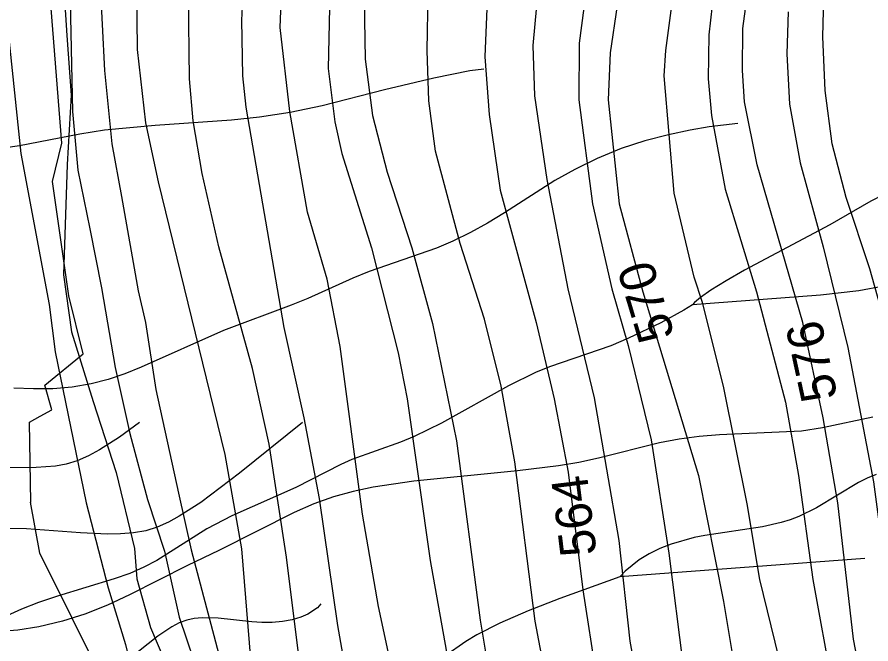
# Model space of a CAD drawing. Extents: x -709584 to -702006, y -1161789 to -1157496.
# Drawn here: x -709283.2 to -709047.8, y -1161005.5 to -1160832.7 of the extents above; entities that cross this region are included whole.
import ezdxf

# ---------------------------------------------------------------- set-up
doc = ezdxf.new("R2010")
doc.units = 0
for name, color, linetype in [('103_hranice KÚ', 7, 'Continuous'), ('120_vrstevnice hlavní', 7, 'Continuous'), ('121_vrstevnice hlavní_popis', 7, 'Continuous'), ('122_vrstevnice základní', 7, 'Continuous'), ('408_BPEJ_linie', 7, 'Continuous'), ('411_akumulovaný odtok', 7, 'Continuous')]:
    doc.layers.add(name, color=color, linetype=linetype)

msp = doc.modelspace()

# ---------------------------------------------------------------- linework, layer by layer
at = {"layer": '103_hranice KÚ'}
msp.add_lwpolyline([(-709272.02, -1160799.36), (-709269.54, -1160837.72), (-709268.34, -1160854.2), (-709269.41, -1160873.36), (-709270.41, -1160903.76), (-709268.23, -1160919.43), (-709262.21, -1160938.65), (-709255.95, -1160958.22), (-709250.87, -1160979.18), (-709250.21, -1160987.55), (-709246.42, -1161000.99), (-709242.46, -1161010.31), (-709232.98, -1161027.29), (-709222.38, -1161046.02), (-709218.04, -1161058.04), (-709217.06, -1161067.22), (-709216.15, -1161082.04), (-709217.68, -1161092.12), (-709215.78, -1161106.54), (-709203.57, -1161124.53), (-709202.27, -1161126.44), (-709193.49, -1161139.37), (-709234.65, -1161164.22), (-709251.02, -1161179.72)], dxfattribs=at)
at = {"layer": '120_vrstevnice hlavní'}
for points in [[(-709250.42, -1160816.46), (-709250.13, -1160841.63), (-709247.82, -1160861.88), (-709244.35, -1160878.08), (-709225.98, -1160953.3), (-709221.35, -1160979.33), (-709218.89, -1161009.71), (-709211.8, -1161040.08), (-709208.62, -1161048.76), (-709200.81, -1161066.12), (-709185.48, -1161096.49), (-709177.23, -1161108.79), (-709155.25, -1161134.97), (-709151.92, -1161140.18), (-709150.18, -1161145.96), (-709151.05, -1161152.62), (-709152.35, -1161156.96), (-709157.13, -1161165.64), (-709167.98, -1161177.06)], [(-708894.31, -1161154.64), (-708908.19, -1161150.59), (-708929.31, -1161139.45), (-708935.1, -1161135.84), (-708945.08, -1161127.59), (-708978.06, -1161094.9), (-708986.59, -1161084.92), (-709008.87, -1161053.97), (-709019.43, -1161034.3), (-709023.62, -1161024.46), (-709030.71, -1160999.87), (-709032.59, -1160990.04), (-709042.57, -1160921.76), (-709048.07, -1160902.09), (-709054.57, -1160882.42), (-709058.48, -1160867.67), (-709060.36, -1160852.91), (-709061.08, -1160838.16), (-709060.65, -1160823.7)], [(-709187.5, -1160828.03), (-709187.21, -1160844.24), (-709185.19, -1160859.86), (-709181.14, -1160875.48), (-709174.34, -1160896.31), (-709168.7, -1160917.14), (-709162.05, -1160949.54), (-709155.54, -1160999), (-709153.66, -1161010), (-709148.45, -1161031.98), (-709141.51, -1161053.97), (-709135.14, -1161070.46), (-709116.19, -1161114.43), (-709104.33, -1161135.84), (-709079.02, -1161168.53), (-709074.53, -1161173.16)], [(-709117.78, -1160829.48), (-709119.66, -1160842.5), (-709120.24, -1160855.52), (-709117.21, -1160884.16), (-709110.7, -1160908.46), (-709095.36, -1160959.08), (-709088.42, -1160993.8), (-709083.36, -1161024.17), (-709074.34, -1161055.36), (-709062.5, -1161079.58), (-709039.24, -1161114.57), (-709034.76, -1161120.51), (-708995.85, -1161166.21), (-708983.41, -1161178.65)]]:
    msp.add_lwpolyline(points, dxfattribs=at)
at = {"layer": '122_vrstevnice základní'}
for points in [[(-709288.17, -1160813.86), (-709282.24, -1160870.27), (-709274.43, -1160911.93), (-709272.7, -1160924.95), (-709264.16, -1160966.6), (-709258.09, -1160990.04), (-709253.32, -1161005.66), (-709243.77, -1161044.42), (-709240.59, -1161061.78), (-709239.86, -1161073.35), (-709241.89, -1161086.66), (-709245.07, -1161094.47), (-709251.72, -1161105.17), (-709257.08, -1161110.67), (-709269.81, -1161117.9), (-709290.63, -1161126.29), (-709303.65, -1161133.96), (-709321.88, -1161148.13), (-709347.33, -1161172.87)], [(-709099.56, -1161178.36), (-709099.99, -1161172), (-709102.16, -1161167.37), (-709120.96, -1161143.07), (-709137.17, -1161115.3), (-709163.35, -1161060.04), (-709168.99, -1161046.16), (-709175.5, -1161027.64), (-709180.12, -1161011.44), (-709183.6, -1160995.24), (-709187.94, -1160969.79), (-709194.16, -1160923.5), (-709197.77, -1160904.99), (-709203.12, -1160886.47), (-709208.04, -1160858.7), (-709210.65, -1160835.56), (-709209.92, -1160817.04)], [(-708958.82, -1161176.92), (-708979.36, -1161163.9), (-708987.17, -1161158.26), (-708993.39, -1161152.76), (-709001.06, -1161144.8), (-709013.21, -1161130.2), (-709033.6, -1161102.14), (-709041.56, -1161089.55), (-709046.62, -1161079.72), (-709056.74, -1161063.52), (-709062.29, -1161052.26), (-709067.83, -1161036.6), (-709071.06, -1161017.81), (-709078.44, -1160987.72), (-709081.91, -1160966.89), (-709088.42, -1160934.49), (-709094.21, -1160911.35), (-709096.52, -1160904.41), (-709102.02, -1160881.26), (-709104.77, -1160848.86), (-709104.33, -1160841.92), (-709101.29, -1160819.07)], [(-709260.4, -1160821.96), (-709259.1, -1160847.42), (-709257.08, -1160867.67), (-709254.47, -1160882.13), (-709249.84, -1160908.17), (-709247.82, -1160916.85), (-709244.93, -1160935.36), (-709238.71, -1160964), (-709235.23, -1160979.62), (-709225.54, -1161016.07)], [(-709196.9, -1160821.67), (-709197.48, -1160846.84), (-709195.6, -1160861.59), (-709193.72, -1160870.27), (-709185.48, -1160896.31), (-709178.1, -1160925.24), (-709175.64, -1160937.96), (-709169.28, -1160982.52), (-709163.06, -1161017.52), (-709160.31, -1161030.25), (-709155.97, -1161046.16), (-709151.2, -1161058.89)], [(-709125.88, -1160821.67), (-709128.2, -1160839.9), (-709128.34, -1160855.52), (-709124.58, -1160884.16), (-709119.23, -1160907.59), (-709114.75, -1160923.21), (-709108.38, -1160949.25), (-709103.46, -1160980.49), (-709099.56, -1161011.73), (-709096.38, -1161027.93), (-709091.89, -1161045.29), (-709083.5, -1161071.33), (-709080.9, -1161077.11), (-709071.5, -1161094.47), (-709051.83, -1161126.29), (-709036.06, -1161147.12), (-709006.26, -1161180.97)], [(-709268.65, -1160823.98), (-709267.92, -1160858.7), (-709266.48, -1160874.9), (-709263.15, -1160891.1), (-709259.97, -1160907.3), (-709256.21, -1160929.29), (-709252.16, -1160947.51), (-709247.24, -1160965.74), (-709242.61, -1160979.91), (-709238.56, -1160998.14), (-709232.34, -1161016.36)], [(-709220.91, -1160824.27), (-709221.35, -1160833.53), (-709221.06, -1160848.86), (-709220.19, -1160857.54), (-709209.63, -1160918.29), (-709204.14, -1160943.17), (-709199.94, -1160965.45), (-709194.88, -1161000.45), (-709189.82, -1161029.09), (-709184.75, -1161048.18), (-709178.68, -1161064.09), (-709165.66, -1161089.55), (-709149.75, -1161111.83), (-709139.62, -1161127.16), (-709131.96, -1161136.42), (-709123.28, -1161151.75), (-709120.1, -1161160.43), (-709119.37, -1161166.21), (-709120.39, -1161172.29), (-709121.54, -1161175.47)], [(-709030.85, -1161175.04), (-709046.18, -1161156.96), (-709080.03, -1161108.93), (-709087.55, -1161095.05), (-709097.39, -1161071.91), (-709102.89, -1161055.71), (-709109.1, -1161032.56), (-709114.17, -1161004.79), (-709117.2, -1160977.02), (-709124, -1160937.68), (-709131.23, -1160907.59), (-709137.02, -1160877.5), (-709140.49, -1160854.36), (-709140.93, -1160840.47), (-709139.48, -1160824.56)], [(-709028.97, -1161066.7), (-709039.39, -1161048.47), (-709045.03, -1161035.46), (-709048.5, -1161025.04), (-709052.55, -1161004.21), (-709056.89, -1160966.6), (-709060.94, -1160943.17), (-709066.58, -1160916.85), (-709079.16, -1160873.45), (-709082.64, -1160856.09), (-709083.21, -1160847.42), (-709083.07, -1160835.84), (-709081.62, -1160824.85)], [(-709173.76, -1161204.69), (-709136.44, -1161161.58), (-709134.56, -1161158.11), (-709133.84, -1161151.46), (-709136.88, -1161144.23), (-709148.16, -1161129.33), (-709159.44, -1161111.83), (-709173.04, -1161093.6), (-709186.92, -1161072.77), (-709193.14, -1161059.76), (-709200.67, -1161036.32), (-709204.71, -1161015.49), (-709208.91, -1160981.65), (-709213.68, -1160950.4), (-709218.31, -1160929.57), (-709227.57, -1160896.02), (-709232.2, -1160875.77), (-709234.66, -1160861.3), (-709235.67, -1160849.73), (-709235.96, -1160826.59)], [(-709047.92, -1161186.75), (-709078.01, -1161154.64), (-709086.83, -1161142.49), (-709103.03, -1161117.03), (-709115.9, -1161091.87), (-709125.45, -1161066.41), (-709131.96, -1161043.27), (-709140.35, -1160999.29), (-709145.99, -1160955.32), (-709149.75, -1160934.49), (-709154.38, -1160915.98), (-709161.03, -1160895.15), (-709167.83, -1160869.69), (-709169.71, -1160855.81), (-709170.14, -1160841.92), (-709169.85, -1160826.01)], [(-709153.66, -1160830.35), (-709154.23, -1160843.66), (-709153.08, -1160859.57), (-709150.04, -1160880.4), (-709140.06, -1160916.85), (-709135.14, -1160937.96), (-709131.23, -1160958.21), (-709127.19, -1160990.61), (-709123.42, -1161014.92), (-709117.78, -1161045.29), (-709112.87, -1161065.54), (-709107.95, -1161081.74), (-709104.19, -1161091.87), (-709095.8, -1161110.09), (-709077.57, -1161141.33), (-709066.44, -1161156.96)], [(-709091.6, -1160829.48), (-709092.47, -1160837.58), (-709092.62, -1160849.73), (-709091.75, -1160859.86), (-709087.99, -1160880.11), (-709079.31, -1160908.46), (-709071.35, -1160938.83), (-709067.74, -1160959.08), (-709063.83, -1160987.72), (-709058.33, -1161017.52), (-709055.15, -1161029.67), (-709045.75, -1161053.97), (-709037.65, -1161069.3), (-709018.27, -1161100.26), (-709005.97, -1161118.19), (-708995.85, -1161131.5), (-708982.25, -1161146.69), (-708972.56, -1161155.65), (-708955.35, -1161167.8), (-708936.54, -1161178.65)], [(-709070.63, -1160831.22), (-709070.92, -1160842.79), (-709070.2, -1160856.67), (-709067.3, -1160872.87), (-709060.94, -1160896.02), (-709054.14, -1160923.79), (-709047.05, -1160960.82), (-709042.71, -1160993.22), (-709040.11, -1161007.1), (-709035.48, -1161025.62), (-709026.08, -1161048.76), (-709020.44, -1161058.45), (-708989.05, -1161101.99), (-708964.17, -1161129.76), (-708951.59, -1161141.77), (-708944.35, -1161147.7)]]:
    msp.add_lwpolyline(points, dxfattribs=at)
at = {"layer": '408_BPEJ_linie'}
msp.add_lwpolyline([(-709259, -1161016.5), (-709277, -1160980.5), (-709279.55, -1160966.46), (-709279.46, -1160966.54), (-709279.83, -1160944.38), (-709276.84, -1160942.75), (-709273.64, -1160941.01), (-709275.62, -1160934.19), (-709265, -1160925.5), (-709269, -1160909.5), (-709273.5, -1160878), (-709270.89, -1160867.4), (-709278.1, -1160776.85)], dxfattribs=at)
at = {"layer": '411_akumulovaný odtok'}
msp.add_line((-709049.49, -1160982), (-709116.99, -1160987), dxfattribs=at)
for points in [[(-709154.49, -1160847), (-709158.39, -1160847.52), (-709168.31, -1160849.49), (-709181.95, -1160852.72), (-709199.08, -1160857.18), (-709207.93, -1160858.97), (-709216.4, -1160860.25), (-709224.07, -1160861.06), (-709245.18, -1160862.54), (-709259.1, -1160863.9), (-709265.92, -1160864.92), (-709282.56, -1160868.17), (-709297.21, -1160870.26)], [(-709084.49, -1160862), (-709092.35, -1160862.96), (-709097.59, -1160863.87), (-709103.61, -1160865.15), (-709110.08, -1160866.83), (-709116.69, -1160868.96), (-709123.29, -1160871.65), (-709129.44, -1160874.66), (-709134.9, -1160877.75), (-709148.82, -1160886.65), (-709153.48, -1160889.47), (-709158.22, -1160892.11), (-709163.07, -1160894.48), (-709167.61, -1160896.36), (-709186.15, -1160902.87), (-709190.69, -1160904.66), (-709203.09, -1160910.24), (-709207.66, -1160912.11), (-709226.35, -1160919.12), (-709248.99, -1160929.18), (-709253.53, -1160931.01), (-709258.12, -1160932.6), (-709262.77, -1160933.85), (-709268.02, -1160934.73), (-709273.35, -1160935.15), (-709278.73, -1160935.22), (-709284.14, -1160935)], [(-709044.23, -1160881.62), (-709047.8, -1160883.46), (-709059.09, -1160889.98), (-709082.61, -1160902.48), (-709087.74, -1160905.38), (-709091.96, -1160908), (-709094.75, -1160909.98), (-709096.47, -1160911.38), (-709096.99, -1160912)], [(-708924.49, -1160897), (-708925.71, -1160896.82), (-708926.97, -1160896.39), (-708935.5, -1160893.01), (-708939.11, -1160892), (-708942.91, -1160891.41), (-708961.24, -1160890.31), (-708985.82, -1160888.48), (-708992.8, -1160888.22), (-708999.67, -1160888.41), (-709003.02, -1160888.8), (-709006.3, -1160889.48), (-709009.55, -1160890.53), (-709012.72, -1160891.88), (-709015.84, -1160893.43), (-709028.15, -1160900.42), (-709034.42, -1160903.65), (-709037.65, -1160904.99), (-709040.92, -1160906.05), (-709044.26, -1160906.89), (-709051.1, -1160908.12), (-709061.65, -1160909.34), (-709096.99, -1160912)], [(-709096.99, -1160912), (-709099.39, -1160913.52), (-709105.74, -1160916.99), (-709114.6, -1160921.25), (-709119.53, -1160923.31), (-709136.39, -1160929.11), (-709140.23, -1160930.69), (-709147.75, -1160934.4), (-709166.24, -1160944.61), (-709173.73, -1160948.3), (-709177.53, -1160949.89), (-709190.91, -1160954.69), (-709193.94, -1160956.08), (-709206.36, -1160962.4), (-709224.03, -1160970.25), (-709230.88, -1160973.76), (-709244.74, -1160982.48), (-709248.3, -1160984.4), (-709252.16, -1160986.07), (-709256.44, -1160987.57), (-709272.08, -1160992.36), (-709277.3, -1160994.1), (-709282.06, -1160995.92), (-709286.1, -1160997.77)], [(-709047.26, -1160943.04), (-709061.13, -1160945.97), (-709066.95, -1160946.83), (-709089.56, -1160947.87), (-709095.1, -1160948.37), (-709100.63, -1160949.07), (-709106.11, -1160950.07), (-709122.86, -1160954.35), (-709128.36, -1160955.48), (-709133.94, -1160956.4), (-709145.26, -1160957.81), (-709173.82, -1160960.66), (-709185.07, -1160962.31), (-709190.59, -1160963.46), (-709195.98, -1160964.95), (-709201.44, -1160966.93), (-709206.78, -1160969.25), (-709227.62, -1160979.75), (-709236.27, -1160983.9), (-709252.23, -1160992.03), (-709258.33, -1160994.81), (-709264.54, -1160997.28), (-709270.67, -1160999.27), (-709277.22, -1161000.81), (-709283.02, -1161001.72), (-709287.68, -1161002.13)], [(-709249.49, -1160944.5), (-709254.98, -1160948.56), (-709260.48, -1160952.05), (-709263.53, -1160953.66), (-709266.64, -1160955), (-709269.73, -1160955.95), (-709272.6, -1160956.48), (-709277.93, -1160956.88), (-709286.07, -1160957.01), (-709313.37, -1160956.91), (-709318.76, -1160957.15), (-709324.05, -1160957.77), (-709326.63, -1160958.33), (-709329.12, -1160959.09), (-709333.96, -1160961.11), (-709338.7, -1160963.51), (-709352.83, -1160971.35), (-709358.75, -1160973.95), (-709362.03, -1160975.06), (-709365.33, -1160975.94), (-709368.31, -1160976.5), (-709373.43, -1160977.02), (-709376.99, -1160977)], [(-709204.49, -1160944.5), (-709221.86, -1160958.44), (-709232.58, -1160966.54), (-709238.51, -1160970.34), (-709241.5, -1160971.94), (-709244.56, -1160973.29), (-709247.71, -1160974.3), (-709251.16, -1160974.93), (-709254.72, -1160975.21), (-709258.34, -1160975.25), (-709265.71, -1160974.89), (-709280.63, -1160973.79), (-709288.07, -1160973.7)], [(-709046.35, -1160958.83), (-709048.8, -1160959.81), (-709051.19, -1160961), (-709062.79, -1160968), (-709067.61, -1160970.42), (-709070.05, -1160971.32), (-709072.55, -1160972.05), (-709077.7, -1160973.2), (-709093.56, -1160975.6), (-709096.49, -1160976.17), (-709102.87, -1160978), (-709106.02, -1160979.24), (-709108.95, -1160980.69), (-709111.66, -1160982.38), (-709115.59, -1160985.5), (-709116.99, -1160987)], [(-709116.99, -1160987), (-709133.55, -1160993.04), (-709142.34, -1160996.44), (-709150.15, -1160999.78), (-709156.45, -1161003.05), (-709159.46, -1161004.89), (-709165.3, -1161008.91)], [(-709199.49, -1160994.5), (-709200.39, -1160995.55), (-709203.07, -1160997.32), (-709204.95, -1160998.17), (-709207.38, -1160998.9), (-709210.07, -1160999.37), (-709212.9, -1160999.59), (-709215.75, -1160999.62), (-709218.48, -1160999.48), (-709227.78, -1160998.44), (-709232.22, -1160998.34), (-709234.36, -1160998.54), (-709236.45, -1160998.98), (-709238.54, -1160999.76), (-709240.56, -1161000.79), (-709244.46, -1161003.35), (-709257.71, -1161013.94)]]:
    msp.add_lwpolyline(points, dxfattribs=at)

# ---------------------------------------------------------------- texts
at = {"layer": '121_vrstevnice hlavní_popis'}
for s, rotation, p in [('570', 106.741, (-709101.84, -1160920.55)), ('576', 102.1974, (-709056.91, -1160937.52)), ('564', 97.0146, (-709123.36, -1160980.76))]:
    msp.add_text(s, height=10, rotation=rotation, dxfattribs=at).set_placement(p)

doc.saveas('drawing.dxf')
